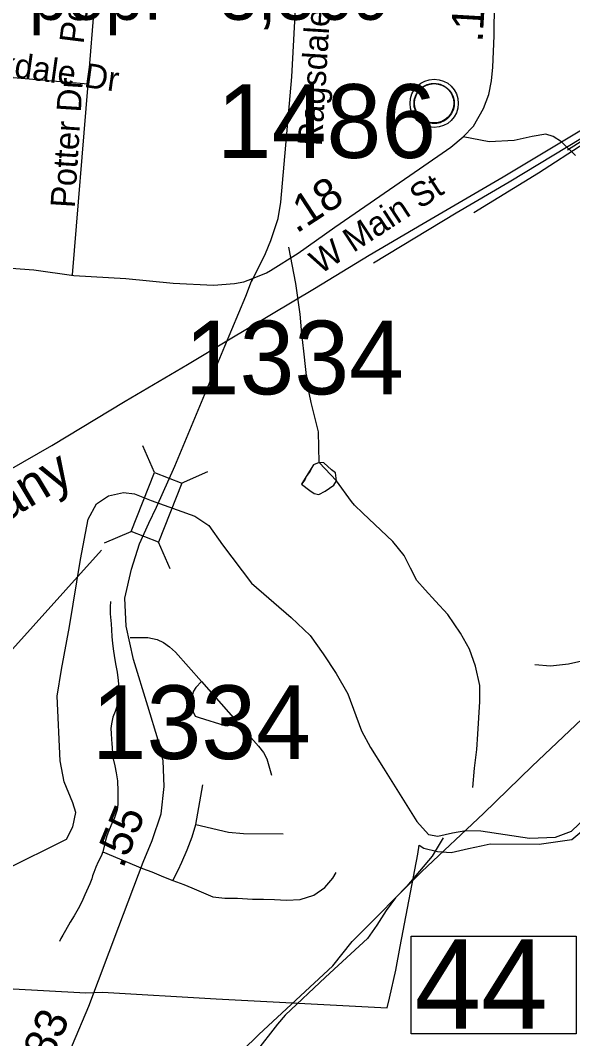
# Model space of a CAD drawing. Extents: x 1662474 to 1856135, y 779280 to 917889.
# Drawn here: x 1721448 to 1723605, y 814512 to 818491 of the extents above; entities that cross this region are included whole.
import ezdxf

# ---------------------------------------------------------------- set-up
doc = ezdxf.new("R2010")
doc.units = 0
for name, color, linetype in [('Cogo Default Point CELL', 7, 'Continuous'), ('Exist Boundary Political City Limit New', 7, 'Continuous'), ('Exist Civil Demographics City Label', 7, 'Continuous'), ('Exist Civil Demographics Community CELL', 7, 'Continuous'), ('Exist Hydrographic Creek Single Shore', 7, 'Continuous'), ('Exist Hydrographic Misc Water Feature', 7, 'Continuous'), ('Exist Railroad Mainline', 7, 'Continuous'), ('Exist Railroad Mainline Label', 7, 'Continuous'), ('Exist Railroad Siding', 7, 'Continuous'), ('Exist Road Non-System Type 51', 7, 'Continuous'), ('Exist Road Non-System Type 51 Label', 7, 'Continuous'), ('Exist Road Secondary Mileage Tenths English Label', 7, 'Continuous'), ('Exist Road Secondary Structure Standard Bridge CELL', 7, 'Continuous'), ('Exist Road Secondary Structure Standard Bridge Number Label', 7, 'Continuous'), ('Exist Road Secondary Type 51 Attributed', 7, 'Continuous'), ('Exist Road Secondary Type 51 Label', 7, 'Continuous'), ('Exist Utilities Electrical Transmission Line', 7, 'Continuous'), ('Map Preparation Boundary City Limit Buffer Line', 7, 'Continuous'), ('Prop DGN Element Guardrail', 7, 'Continuous')]:
    doc.layers.add(name, color=color, linetype=linetype)

msp = doc.modelspace()

# ---------------------------------------------------------------- linework, layer by layer
at = {"layer": 'Exist Boundary Political City Limit New'}
msp.add_lwpolyline([(1721040, 815074.6), (1721039.9, 815069), (1720993.4, 814727.8), (1721194, 814718.7), (1721252.8, 814716), (1721704, 814691.2), (1721768.5, 814694.5), (1722213.2, 814668.4), (1722881.1, 814633.2), (1722889.4, 814670.6), (1722914.1, 814779.9), (1722931.9, 814872.4), (1723001.2, 815233.5), (1723006.1, 815268.5), (1723023.8, 815256.4), (1723077, 815243.7), (1723131.5, 815239.9), (1723198.4, 815254.9), (1723248.1, 815265.7), (1723282.9, 815273.9), (1723474.1, 815272.7), (1723602.9, 815290.6), (1723720.4, 815389.7)], dxfattribs=at)
at = {"layer": 'Exist Civil Demographics Community CELL'}
msp.add_lwpolyline([(1722986.9, 818179.4), (1722987.9, 818185), (1722989.7, 818191.6), (1722992.6, 818198.8), (1722995.5, 818204.5), (1722998.9, 818210.3), (1723002.6, 818215.4), (1723006.6, 818219.7), (1723011.2, 818224.3), (1723016.7, 818228.9), (1723022.1, 818232.6), (1723027, 818235.5), (1723032.1, 818237.9), (1723037.5, 818240.2), (1723043.2, 818242), (1723047.5, 818243.2), (1723052.3, 818243.9), (1723056.5, 818244.6), (1723062.8, 818244.9), (1723067.3, 818244.8), (1723072.9, 818244.5), (1723077.8, 818243.8), (1723082.7, 818242.8), (1723087.8, 818241.4), (1723092.9, 818239.5), (1723099.6, 818236.6), (1723105.8, 818233.1), (1723110.9, 818229.5), (1723116.1, 818225.5), (1723119.4, 818222.4), (1723123.5, 818218), (1723127.4, 818213.3), (1723130.4, 818208.7), (1723133.6, 818203.7), (1723136, 818198.5), (1723138.1, 818193.5), (1723139.6, 818188.5), (1723140.9, 818183.9), (1723142, 818177.9), (1723142.6, 818173.2), (1723142.9, 818167.2), (1723142.7, 818161.4), (1723142.1, 818155.7), (1723141.2, 818150.2), (1723139.5, 818144), (1723137.7, 818138.2), (1723135.4, 818133.1), (1723132.2, 818127.1), (1723128.9, 818121.8), (1723125.5, 818117.1), (1723121.3, 818112.4), (1723116, 818107.4), (1723110.9, 818103.3), (1723105.9, 818099.8), (1723101.6, 818097.3), (1723094.8, 818094.1), (1723087.6, 818091.4), (1723081.7, 818089.9), (1723075.1, 818088.6), (1723070.7, 818088.2), (1723066.2, 818087.9), (1723060.6, 818087.9), (1723056.3, 818088.3), (1723050.7, 818089), (1723044.8, 818090.3), (1723040.2, 818091.7), (1723035, 818093.5), (1723030.4, 818095.5), (1723026.5, 818097.8), (1723019.7, 818101.8), (1723014.1, 818106.1), (1723009.2, 818110.6), (1723004.7, 818115.4), (1723001.6, 818119.4), (1722998.6, 818123.6), (1722994.5, 818130.7), (1722992.8, 818134.2), (1722991, 818138.2), (1722988.5, 818146.4), (1722986.9, 818153.5), (1722986.2, 818158.6), (1722985.9, 818165), (1722985.8, 818169.7), (1722986.4, 818176.1)], close=True, dxfattribs=at)
for centre, radius in [((1723064.5, 818167), 94.3), ((1723064.3, 818167.3), 76.7)]:
    msp.add_circle(centre, radius, dxfattribs=at)
at = {"layer": 'Exist Hydrographic Creek Single Shore'}
msp.add_lwpolyline([(1721386.8, 815172.4), (1721627.4, 815292.1), (1721653.1, 815339.8), (1721663.9, 815395.8), (1721653.1, 815433.8), (1721619.5, 815515.7), (1721603.8, 815597.3), (1721592.2, 815850.9), (1721609, 815954.5), (1721640.2, 816122.2), (1721683.2, 816384.7), (1721713.2, 816542.2), (1721745.5, 816601.8), (1721792.5, 816633), (1721850.8, 816646.4), (1721893.8, 816640.9), (1721958.6, 816615.1), (1722129, 816553.8), (1722183.5, 816517.2), (1722237.1, 816442.2), (1722351.2, 816291.5), (1722505.9, 816157.4), (1722579.9, 816087.3), (1722630.5, 816015.7), (1722681.5, 815939.3), (1722726.9, 815859.8), (1722781.1, 815715.4), (1722815.2, 815650.6), (1722866, 815568.7), (1722997.1, 815360.6), (1723042.6, 815309.9), (1723079.1, 815303.4), (1723136, 815316.5), (1723188.2, 815325.7), (1723246.8, 815324.4), (1723436.5, 815295.8), (1723537.9, 815299.9), (1723600.4, 815323.3), (1723657.2, 815376.3)], dxfattribs=at)
at = {"layer": 'Exist Hydrographic Misc Water Feature'}
for p, q in [((1722615.1, 816764), (1722612.4, 816884.1)), ((1722682.7, 816691.4), (1722615.1, 816764)), ((1722741.8, 816610.7), (1722682.7, 816691.4))]:
    msp.add_line(p, q, dxfattribs=at)
for points in [[(1722612.4, 816884.1), (1722583.5, 816998.4), (1722570.2, 817066.5), (1722555.4, 817198.7), (1722548, 817266.8), (1722540.6, 817342.9), (1722523.8, 817463.1), (1722497.2, 817605.4)], [(1722615.1, 816764), (1722593.1, 816754.2), (1722579, 816728.4), (1722564.6, 816708.5), (1722558.7, 816696.5), (1722546.4, 816678.6), (1722578.2, 816654.3), (1722596, 816642.1), (1722614, 816638), (1722638.2, 816651.8), (1722672.5, 816675.4), (1722682.7, 816691.4)], [(1722615.1, 816764), (1722593.1, 816754.2), (1722564.6, 816708.5), (1722546.4, 816678.6), (1722578.2, 816654.3), (1722596, 816642.1), (1722614, 816638), (1722638.2, 816651.8), (1722672.5, 816675.4), (1722682.7, 816691.4)], [(1722682.7, 816691.4), (1722678.8, 816723.4), (1722663.1, 816735.5), (1722633.3, 816761.8), (1722615.1, 816764)], [(1723215.5, 815493.9), (1723222.2, 815569.9), (1723230.8, 815641.8), (1723235.4, 815701.8), (1723242.5, 815829.8), (1723243.1, 815891.8), (1723225.9, 815968), (1723202.5, 816034.2), (1723167.1, 816096.6), (1723117.9, 816169.1), (1723070.3, 816221.6), (1723028.7, 816266), (1722997.1, 816302.2), (1722971.5, 816350.5), (1722947.9, 816400.8), (1722902.4, 816455.2), (1722833, 816521.9), (1722785.5, 816566.3), (1722753.7, 816596.6), (1722741.8, 816610.7)], [(1723099.6, 815297), (1723056.8, 815225.4), (1722957.7, 815108.2), (1722913.2, 815062.7), (1722876.7, 815013), (1722840.2, 814955.3), (1722803.7, 814903.6), (1722739.1, 814844.2), (1722640.1, 814753.1), (1722482.8, 814604.6), (1722452.5, 814568.8), (1722365.3, 814457.6)]]:
    msp.add_lwpolyline(points, dxfattribs=at)
at = {"layer": 'Exist Railroad Mainline'}
for points in [[(1722261.2, 817242.5), (1722596.6, 817443.1), (1722810.7, 817573.6), (1723021.5, 817697.6), (1723334.5, 817879.5), (1723562, 818016.6), (1723735.7, 818120.5), (1723937.9, 818239.5)], [(1719386.1, 814234.3), (1719525.3, 814515.1), (1719727.1, 814909.9), (1719838.8, 815136.9), (1719949, 815357.9), (1720035.3, 815522.3), (1720101.4, 815631.7), (1720181.8, 815748.1), (1720260.8, 815861), (1720344.7, 815963.3), (1720430.7, 816058.7), (1720480.4, 816110.1), (1720563.2, 816189.1), (1720656.8, 816269.8), (1720748.6, 816341.8), (1720820.8, 816392.6), (1720921.4, 816456.4), (1721046.9, 816529.5), (1721290.5, 816669.9), (1721571, 816829.6), (1721856.7, 817003.3), (1722100.3, 817147.2), (1722261.2, 817242.5)]]:
    msp.add_lwpolyline(points, dxfattribs=at)
at = {"layer": 'Exist Railroad Siding'}
for points in [[(1723937.9, 818239.5), (1723854.2, 818152.6), (1723766.7, 818089.7), (1723653.5, 818011.2), (1723472.2, 817893.8), (1723219.9, 817739.4)], [(1723700.2, 818066.7), (1723357.6, 817859.4), (1723150, 817738.2), (1722827.3, 817542.6)]]:
    msp.add_lwpolyline(points, dxfattribs=at)
at = {"layer": 'Exist Road Non-System Type 51'}
for p, q in [((1721712.1, 818242.4), (1721772, 818961)), ((1721712.1, 818242.4), (1721353.9, 818272.6)), ((1721651, 817496.8), (1721712.1, 818242.4)), ((1722155.4, 815907.8), (1722289.9, 815756.1)), ((1722133.1, 815349.2), (1722161, 815503.6)), ((1721769.9, 815242.7), (1721925, 815177.4))]:
    msp.add_line(p, q, dxfattribs=at)
for points in [[(1722351.8, 817472.6), (1722405.1, 817580.2), (1722425.8, 817631.4), (1722454.9, 817717.2), (1722465.4, 817780.4), (1722509, 818271), (1722525.8, 818586.2)], [(1723584.9, 817984.7), (1723762.2, 818096.8), (1723856.1, 818145), (1723887.4, 818291.8), (1723898.1, 818375.2)], [(1721799.6, 816220.9), (1721798.5, 816200.2), (1721798.5, 816172.6), (1721801.9, 816133.5), (1721803.8, 816109.4), (1721805.1, 816084.4), (1721807.6, 816055.9), (1721811.6, 816025.9), (1721813.8, 816009.9), (1721819.8, 815977.6), (1721825.9, 815943.8), (1721830, 815911.2), (1721832.1, 815882.1), (1721833.4, 815854), (1721829.8, 815827.2), (1721817.6, 815790.4), (1721808.5, 815768.4), (1721803.5, 815742.9), (1721801.6, 815724.6), (1721802.1, 815704.9), (1721803.8, 815681.9), (1721805.6, 815665.8), (1721806.1, 815648.5), (1721807.4, 815628.5), (1721810.9, 815605.7), (1721816.9, 815578.9), (1721822.1, 815550.6), (1721827.4, 815520.1), (1721829.1, 815479.2), (1721829.1, 815453.4), (1721828.6, 815428.5), (1721825.9, 815406.8), (1721815.9, 815374.8), (1721805.1, 815353.4), (1721794.9, 815328.8), (1721786.1, 815305.2), (1721780.4, 815287.1), (1721769.9, 815242.7)], [(1721876.8, 816079.2), (1721946.2, 816079.4), (1721982.8, 816071.9), (1722006.9, 816060.2), (1722030.8, 816044), (1722053.4, 816023), (1722155.4, 815907.8)], [(1723711.4, 816003.4), (1723589.2, 815975.5), (1723519.5, 815968.4), (1723458.4, 815972.4)], [(1722155.4, 815907.8), (1722133.4, 815884.7), (1722123.6, 815870.5), (1722120.9, 815856.6), (1722122.1, 815798.6), (1722122.9, 815789.4), (1722131, 815772.1), (1722145.8, 815766.9), (1722246.2, 815735.9), (1722257.6, 815734.6), (1722265.9, 815738.8), (1722289.9, 815756.1)], [(1722289.9, 815756.1), (1722378.5, 815655.6), (1722397.4, 815630.6), (1722411.1, 815605.4), (1722428.6, 815542.4)], [(1722043.1, 815130.4), (1722064.4, 815170.8), (1722078.6, 815201.8), (1722099, 815249.8), (1722119, 815301), (1722133.1, 815349.2)], [(1722133.1, 815349.2), (1722261.5, 815319.1), (1722319.2, 815313.6), (1722474.4, 815312.5)], [(1721769.9, 815242.7), (1721763.1, 815224.9), (1721751.8, 815203.9), (1721742.1, 815181.9), (1721734.8, 815161.9), (1721730.2, 815148.8), (1721726.6, 815137.4), (1721719, 815117.8), (1721700.1, 815075), (1721688, 815047.2), (1721674.1, 815019.6), (1721657.6, 814992.1), (1721642.9, 814966.9), (1721623.6, 814935.4), (1721613.5, 814916.4), (1721605.9, 814903.9), (1721600.6, 814892.6)], [(1721925, 815177.4), (1721961, 815163.7), (1722006.4, 815144.5), (1722043.1, 815130.4)], [(1722043.1, 815130.4), (1722057.2, 815125.7), (1722086.1, 815114.4), (1722117.6, 815101.5), (1722154.1, 815085.5), (1722200.1, 815066.9), (1722246.8, 815060.9), (1722296.6, 815060.9), (1722355.1, 815057.9), (1722398, 815057.2), (1722440.2, 815055.9), (1722487.5, 815053.8), (1722540.8, 815056.4), (1722593.8, 815072.4), (1722637.4, 815103.1), (1722668.6, 815139), (1722681.4, 815161.9)]]:
    msp.add_lwpolyline(points, dxfattribs=at)
at = {"layer": 'Exist Road Secondary Structure Standard Bridge CELL'}
for p, q in [((1721971.8, 816725), (1721926.7, 816828.8)), ((1722077, 816683.5), (1722180.8, 816728.6)), ((1721776.5, 816449.5), (1721880.3, 816494.6)), ((1722033.1, 816348.3), (1721988, 816452.1))]:
    msp.add_line(p, q, dxfattribs=at)
msp.add_lwpolyline([(1721880.3, 816494.6), (1721971.3, 816725.2), (1722079, 816682.7), (1721988, 816452.1)], close=True, dxfattribs=at)
at = {"layer": 'Exist Road Secondary Structure Standard Bridge Number Label'}
msp.add_line((1721764.9, 816421.7), (1720248.9, 814737.3), dxfattribs=at)
msp.add_lwpolyline([(1722974.9, 814913.3), (1723619, 814913.3), (1723619, 814531), (1722974.9, 814531)], close=True, dxfattribs=at)
at = {"layer": 'Exist Road Secondary Type 51 Attributed'}
for points in [[(1723177.7, 818036.2), (1723218.7, 818077.8), (1723257.3, 818146.8), (1723277.7, 818201.8), (1723289.1, 818254.4), (1723293.8, 818308.8), (1723298.6, 818430.8), (1723300.6, 818562.9), (1723306.6, 818788.9), (1723324.7, 818879), (1723346.7, 818937), (1723366.7, 818973)], [(1722355.3, 817482.3), (1722408.9, 817504.3), (1722425.1, 817513.5), (1722533.1, 817581.2), (1722675.9, 817682.9), (1723007.5, 817910.5), (1723129.8, 817995.9), (1723177.7, 818036.2)], [(1723617, 817962.9), (1723562, 818016.6), (1723529.4, 818038), (1723500.8, 818047), (1723447.1, 818038), (1723377.4, 818021.9), (1723279, 818016.6), (1723177.7, 818036.2)], [(1720278.6, 817603.5), (1720686, 817576.4), (1720945.1, 817554), (1721107, 817546.7), (1721287.4, 817532), (1721500.3, 817517), (1721657, 817494), (1721860.4, 817483.1)], [(1721860.4, 817483.1), (1722044.8, 817464.9), (1722202.7, 817456), (1722284.2, 817463.7), (1722321.2, 817469), (1722355.3, 817482.3)], [(1721979.6, 816588.7), (1722051.2, 816749.1), (1722246.1, 817218), (1722328.4, 817413.9), (1722355.3, 817482.3)], [(1720784, 812571.2), (1720912.6, 812869.4), (1721009.3, 813093.4), (1721265, 813615.5), (1721431.7, 813982.1), (1721587.4, 814337.6), (1721715.2, 814639.7), (1721831.9, 814950.7), (1721928, 815202.4), (1721962.7, 815286.2), (1721997.4, 815390.2), (1722009, 815497.2), (1722006.1, 815598.3), (1721985.8, 815679.2), (1721945.3, 815812.1), (1721890.4, 815994.1), (1721861.5, 816124.1), (1721855.7, 816233.9), (1721881.7, 816347.2), (1721913.5, 816445.4), (1721949.3, 816526.9), (1721979.6, 816588.7)]]:
    msp.add_lwpolyline(points, dxfattribs=at)
at = {"layer": 'Exist Utilities Electrical Transmission Line'}
msp.add_lwpolyline([(1722056.4, 814211.5), (1722378.9, 814528.9), (1722668.3, 814796.8), (1722743.8, 814891.4), (1723015.9, 815165.2), (1723256.8, 815392.1), (1723447.4, 815577.2), (1723666.2, 815783.8), (1724225, 816289.8), (1724598.3, 816650.1), (1725333.8, 817353.7), (1726207.1, 818174.9), (1726600.6, 818559.1), (1727046.2, 818970.5), (1727339.2, 819336.1), (1727602, 819684.3), (1727958.2, 819833.3), (1728373.4, 820206.4), (1728482, 820282), (1728773.5, 820525.9), (1729250, 820911.2), (1729725.3, 821278.5)], dxfattribs=at)
at = {"layer": 'Map Preparation Boundary City Limit Buffer Line'}
msp.add_lwpolyline([(1721040, 815074.6), (1721039.9, 815069), (1720993.4, 814727.8), (1721194, 814718.7), (1721252.8, 814716), (1721704, 814691.2), (1721768.5, 814694.5), (1722213.2, 814668.4), (1722881.1, 814633.2), (1722889.4, 814670.6), (1722914.1, 814779.9), (1722931.9, 814872.4), (1723001.2, 815233.5), (1723006.1, 815268.5), (1723023.8, 815256.4), (1723077, 815243.7), (1723131.5, 815239.9), (1723198.4, 815254.9), (1723248.1, 815265.7), (1723282.9, 815273.9), (1723474.1, 815272.7), (1723602.9, 815290.6), (1723720.4, 815389.7)], dxfattribs=at)

# ---------------------------------------------------------------- texts
at = {"layer": 'Cogo Default Point CELL'}
for s, p in [('1486', (1722215.3, 817953.7)), ('1334', (1722089.7, 817030)), ('1334', (1721726.4, 815605))]:
    msp.add_text(s, height=288, dxfattribs=at).set_placement(p)
at = {"layer": 'Exist Civil Demographics City Label'}
msp.add_text('pop.   3,369', height=200, dxfattribs=at).set_placement((1721482.2, 818493.3))
at = {"layer": 'Exist Railroad Mainline Label'}
msp.add_text('Company', height=150, rotation=30.9251, dxfattribs=at).set_placement((1720926.5, 816252.1))
at = {"layer": 'Exist Road Non-System Type 51 Label'}
for s, rotation, p in [('Potter Dr', 82.8008, (1721694.1, 818396.7)), ('Ragsdale Rd', 86.4691, (1722625.7, 817998.2)), ('Brookdale Dr', 351.9784, (1721091.8, 818315.7)), ('Potter Dr', 86.358, (1721660.1, 817756.6))]:
    msp.add_text(s, height=95, rotation=rotation, dxfattribs=at).set_placement(p)
at = {"layer": 'Exist Road Secondary Mileage Tenths English Label'}
for s, rotation, p in [('.16', 86.65, (1723253.3, 818403.7)), ('.18', 33.1589, (1722526.1, 817656.5)), ('.83', 67.0657, (1721551.2, 814378.4))]:
    msp.add_text(s, height=125, rotation=rotation, dxfattribs=at).set_placement(p)
at = {"layer": 'Exist Road Secondary Structure Standard Bridge Number Label'}
msp.add_text('44', height=350, dxfattribs=at).set_placement((1722987.4, 814550.8))
at = {"layer": 'Exist Road Secondary Type 51 Label'}
msp.add_text('W Main St', height=95, rotation=33.197, dxfattribs=at).set_placement((1722618.8, 817496.8))
at = {"layer": 'Prop DGN Element Guardrail'}
msp.add_text('.55', height=125, rotation=67.5052, dxfattribs=at).set_placement((1721848.6, 815174.1))

doc.saveas('drawing.dxf')
